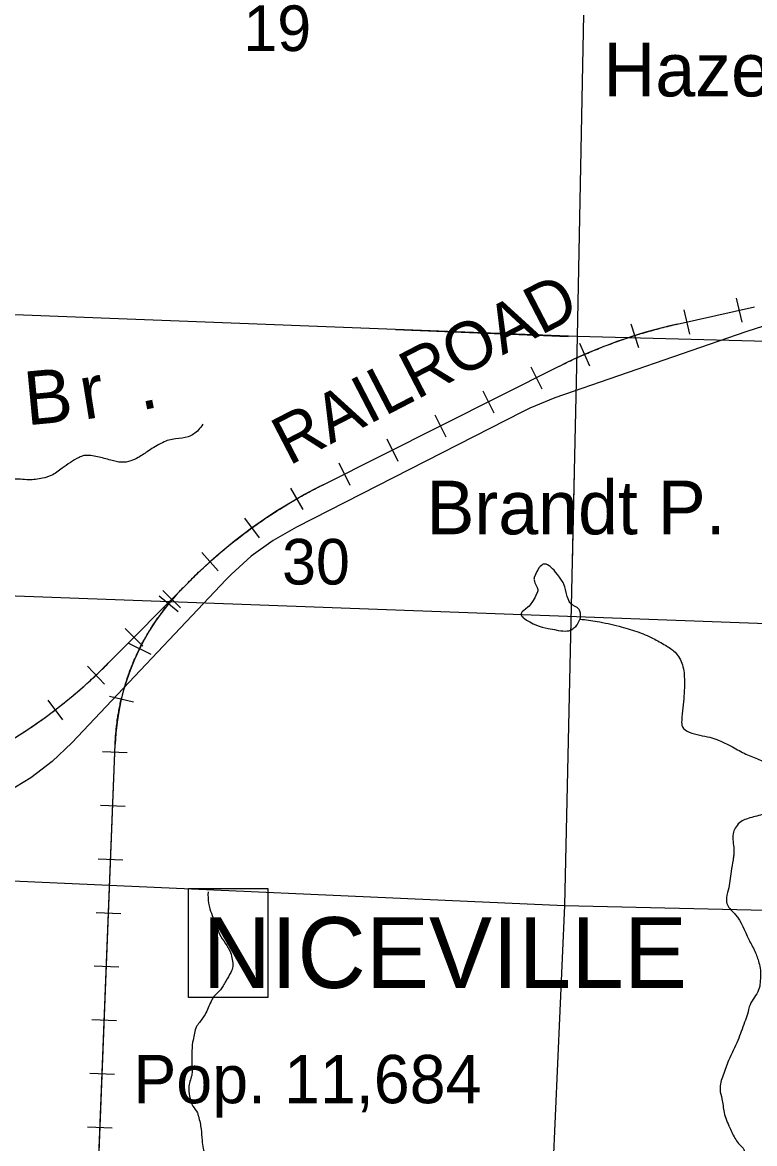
# Model space of a CAD drawing. Extents: x 1219626 to 1426462, y 456797 to 752399.
# Drawn here: x 1341318 to 1348140, y 566519 to 576968 of the extents above; entities that cross this region are included whole.
import ezdxf

# ---------------------------------------------------------------- set-up
doc = ezdxf.new("R2010")
doc.units = 0
for name, color, linetype in [('Cities Incorporated Area', 7, 'Continuous'), ('Lakes and Ponds', 7, 'Continuous'), ('Masks', 7, 'Continuous'), ('Masks for Text', 7, 'Continuous'), ('Narrow River Creek and Branch and Slough', 7, 'Continuous'), ('Narrow River Creek and Branch and Slough Text', 7, 'Continuous'), ('Other Incorporated Names', 7, 'Continuous'), ('Populations', 7, 'Continuous'), ('Railroads', 7, 'Continuous'), ('Railroads Text', 7, 'Continuous'), ('Section Lines', 7, 'Continuous'), ('Section Numbers', 7, 'Continuous')]:
    doc.layers.add(name, color=color, linetype=linetype)

msp = doc.modelspace()

# ---------------------------------------------------------------- linework, layer by layer
at = {"layer": 'Cities Incorporated Area'}
msp.add_line((1339773, 571677), (1348335, 571362), dxfattribs=at)
at = {"layer": 'Lakes and Ponds'}
msp.add_lwpolyline([(1346488, 571354), (1346503, 571384), (1346510, 571396), (1346515, 571408), (1346517, 571419), (1346519, 571430), (1346518, 571448), (1346517, 571462), (1346511, 571481), (1346508, 571489), (1346504, 571497), (1346496, 571506), (1346487, 571514), (1346469, 571525), (1346440, 571540), (1346428, 571549), (1346423, 571555), (1346418, 571560), (1346412, 571572), (1346402, 571595), (1346395, 571616), (1346385, 571655), (1346378, 571684), (1346372, 571707), (1346366, 571723), (1346355, 571747), (1346348, 571759), (1346341, 571771), (1346322, 571797), (1346303, 571822), (1346286, 571844), (1346271, 571862), (1346257, 571876), (1346245, 571888), (1346234, 571897), (1346225, 571904), (1346209, 571914), (1346197, 571918), (1346189, 571920), (1346176, 571919), (1346170, 571918), (1346165, 571915), (1346153, 571907), (1346142, 571897), (1346134, 571887), (1346120, 571867), (1346111, 571850), (1346098, 571823), (1346087, 571796), (1346085, 571788), (1346084, 571780), (1346085, 571772), (1346088, 571758), (1346093, 571745), (1346114, 571702), (1346117, 571691), (1346119, 571683), (1346120, 571671), (1346117, 571660), (1346103, 571628), (1346091, 571606), (1346071, 571572), (1346050, 571541), (1346039, 571528), (1346028, 571518), (1346005, 571500), (1345989, 571487), (1345978, 571478), (1345972, 571470), (1345968, 571465), (1345965, 571457), (1345964, 571449), (1345966, 571443), (1345969, 571438), (1345976, 571427), (1345985, 571418), (1345995, 571411), (1346014, 571398), (1346046, 571380), (1346077, 571364), (1346102, 571353), (1346123, 571345), (1346161, 571333), (1346218, 571320), (1346276, 571309), (1346309, 571302), (1346334, 571298), (1346352, 571296), (1346381, 571295), (1346395, 571296), (1346408, 571299), (1346420, 571302), (1346430, 571306), (1346446, 571315), (1346457, 571324), (1346473, 571338), (1346488, 571354)], dxfattribs=at)
at = {"layer": 'Masks'}
for p, q in [((1344795, 574105), (1346403, 574042)), ((1346458, 572776), (1346439, 571927))]:
    msp.add_line(p, q, dxfattribs=at)
at = {"layer": 'Masks for Text'}
msp.add_lwpolyline([(1342864, 568896), (1343604, 568896), (1343604, 567879), (1342864, 567879)], close=True, dxfattribs=at)
at = {"layer": 'Narrow River Creek and Branch and Slough'}
for points in [[(1343000, 573222), (1342958, 573170), (1342863, 573106), (1342745, 573086), (1342683, 573075), (1342624, 573051), (1342493, 572975), (1342396, 572913), (1342327, 572881), (1342241, 572868), (1342140, 572888), (1342016, 572919), (1341954, 572930), (1341891, 572930), (1341846, 572913), (1341687, 572812), (1341587, 572746), (1341504, 572719), (1341376, 572705), (1341227, 572708), (1341134, 572688), (1340926, 572688), (1340871, 572684), (1340795, 572733), (1340743, 572788), (1340646, 572895), (1340581, 572951), (1340439, 573041), (1340383, 573082), (1340325, 573131), (1340231, 573165), (1340089, 573172), (1339885, 573176), (1339816, 573151), (1339746, 573106), (1339677, 573048), (1339577, 572989), (1339515, 572926), (1339497, 572830), (1339518, 572774), (1339567, 572705), (1339636, 572663), (1339715, 572636), (1339736, 572594), (1339726, 572515), (1339670, 572421), (1339605, 572356), (1339504, 572297), (1339411, 572279), (1339297, 572300), (1339203, 572279), (1339127, 572255), (1339055, 572234), (1338999, 572196), (1338944, 572141), (1338889, 572131), (1338844, 572165), (1338778, 572224), (1338702, 572345), (1338643, 572418), (1338581, 572439), (1338470, 572525), (1338380, 572587), (1338308, 572629), (1338207, 572663), (1338014, 572698), (1337910, 572722), (1337685, 572798), (1337578, 572864), (1337481, 572944), (1337425, 572982), (1337297, 573003), (1337155, 572999), (1337010, 572975), (1336882, 572895), (1336813, 572837), (1336730, 572757), (1336619, 572670), (1336491, 572591), (1336426, 572560), (1336301, 572567), (1336166, 572608), (1335962, 572695), (1335834, 572743), (1335803, 572781), (1335717, 572816), (1335672, 572833), (1335617, 572819), (1335557, 572791)], [(1346514, 571407), (1346673, 571385), (1346877, 571340), (1347043, 571291), (1347195, 571226), (1347309, 571163), (1347399, 571098), (1347468, 570980), (1347486, 570831), (1347482, 570693), (1347461, 570464), (1347468, 570402), (1347531, 570354), (1347724, 570305), (1347935, 570215), (1348060, 570149), (1348181, 570098), (1348289, 570045), (1348351, 569983), (1348399, 569862), (1348406, 569779), (1348386, 569706), (1348347, 569657), (1348309, 569630), (1348254, 569602), (1348195, 569581), (1348064, 569543), (1348012, 569519), (1347967, 569471), (1347943, 569422), (1347946, 569280), (1347946, 569208), (1347939, 569163), (1347922, 569055), (1347894, 568882), (1347877, 568785), (1347894, 568730), (1347960, 568654), (1348085, 568422), (1348143, 568311), (1348181, 568204), (1348195, 568135), (1348195, 568093), (1348178, 567951), (1348098, 567813), (1348074, 567726), (1348047, 567650), (1347984, 567480), (1347898, 567294), (1347846, 567155), (1347818, 567024), (1347836, 566937), (1347856, 566809), (1347908, 566667), (1347964, 566557), (1348002, 566508), (1348040, 566463), (1348060, 566380), (1348077, 566347)], [(1343047, 568864), (1343052, 568760), (1343065, 568707), (1343095, 568624), (1343132, 568534), (1343155, 568472), (1343208, 568387), (1343257, 568299), (1343273, 568234), (1343278, 568170), (1343259, 568114), (1343213, 568034), (1343188, 567990), (1343162, 567951), (1343098, 567886), (1343075, 567842), (1343049, 567784), (1343019, 567722), (1342959, 567637), (1342932, 567593), (1342918, 567533), (1342904, 567464), (1342897, 567355), (1342897, 567226), (1342897, 567168), (1342869, 567055), (1342869, 567005), (1342886, 566919), (1342906, 566868), (1342948, 566806), (1342957, 566774), (1342973, 566712), (1342982, 566654), (1342992, 566550), (1343001, 566472), (1343015, 566428), (1343038, 566393), (1343061, 566379), (1343082, 566342), (1343077, 566310), (1343077, 566238), (1343089, 566201), (1343107, 566166), (1343160, 566131), (1343188, 566113), (1343225, 566044), (1343250, 565965), (1343273, 565887), (1343282, 565815), (1343298, 565769), (1343342, 565682), (1343391, 565580), (1343437, 565504), (1343480, 565415), (1343531, 565351), (1343584, 565265), (1343621, 565178), (1343646, 565058), (1343658, 565005), (1343672, 564975), (1343725, 564915), (1343759, 564882), (1343773, 564852), (1343799, 564780), (1343812, 564720), (1343810, 564677), (1343794, 564607), (1343778, 564570), (1343669, 564527), (1343582, 564487), (1343506, 564462), (1343434, 564418), (1343409, 564384), (1343374, 564328), (1343361, 564268), (1343344, 564208), (1343351, 564121), (1343361, 564017), (1343363, 563994), (1343340, 563938), (1343294, 563862), (1343238, 563779), (1343227, 563749), (1343218, 563666), (1343225, 563528), (1343225, 563470), (1343257, 563380), (1343280, 563276), (1343287, 563184), (1343278, 563092), (1343257, 562995)]]:
    msp.add_spline(points, degree=3, dxfattribs=at)
at = {"layer": 'Railroads'}
for p, q in [((1347969, 574397), (1348020, 574173)), ((1347420, 574156), (1348140, 574318)), ((1347481, 574288), (1347532, 574063)), ((1346988, 574159), (1347058, 573939)), ((1348057, 574085), (1346280, 573468)), ((1346509, 573979), (1346601, 573768)), ((1344119, 572659), (1346318, 573763)), ((1346054, 573759), (1346157, 573553)), ((1345607, 573534), (1345710, 573329)), ((1345977, 573339), (1343871, 572265)), ((1345160, 573310), (1345263, 573105)), ((1344713, 573086), (1344816, 572880)), ((1344266, 572862), (1344369, 572656)), ((1343817, 572627), (1343932, 572428)), ((1343387, 572349), (1343523, 572163)), ((1342989, 572027), (1343143, 571856)), ((1343217, 571776), (1341777, 570254)), ((1342118, 570996), (1342861, 571746)), ((1342627, 571673), (1342790, 571511)), ((1342592, 571624), (1342770, 571478)), ((1342275, 571318), (1342439, 571156)), ((1342307, 571183), (1342513, 571081)), ((1341924, 570967), (1342082, 570800)), ((1341553, 570651), (1341692, 570469)), ((1342128, 570690), (1342352, 570636)), ((1341961, 564672), (1342182, 570241)), ((1342064, 570172), (1342294, 570163)), ((1342044, 569673), (1342274, 569664)), ((1342024, 569173), (1342254, 569164)), ((1342005, 568674), (1342234, 568664)), ((1341985, 568174), (1342215, 568165)), ((1341965, 567674), (1342195, 567665)), ((1341945, 567175), (1342175, 567166)), ((1341925, 566675), (1342155, 566666))]:
    msp.add_line(p, q, dxfattribs=at)
for points in [[(1346693, 573931), (1346711, 573938), (1346730, 573946), (1346748, 573953), (1346766, 573960), (1346785, 573967), (1346803, 573973), (1346821, 573980), (1346840, 573987), (1346858, 573994), (1346877, 574000), (1346895, 574007), (1346914, 574013), (1346932, 574019), (1346951, 574026), (1346969, 574032), (1346988, 574038), (1347007, 574044), (1347025, 574050), (1347044, 574056), (1347063, 574061), (1347081, 574067), (1347100, 574073), (1347119, 574078), (1347138, 574084), (1347157, 574089), (1347176, 574094), (1347194, 574100), (1347213, 574105), (1347232, 574110), (1347251, 574115), (1347270, 574120), (1347289, 574125), (1347308, 574130), (1347327, 574134), (1347346, 574139), (1347365, 574143), (1347384, 574148), (1347403, 574152), (1347420, 574156), (1348140, 574318)], [(1349704, 574058), (1349465, 574136), (1349219, 574188), (1348969, 574215), (1348718, 574215), (1348468, 574188), (1348223, 574136), (1348057, 574085)], [(1342889, 571774), (1342903, 571788), (1342917, 571802), (1342931, 571815), (1342945, 571829), (1342959, 571843), (1342973, 571856), (1342987, 571869), (1343002, 571883), (1343016, 571896), (1343031, 571909), (1343045, 571923), (1343060, 571936), (1343074, 571949), (1343089, 571962), (1343104, 571975), (1343118, 571988), (1343133, 572001), (1343148, 572013), (1343163, 572026), (1343178, 572039), (1343193, 572051), (1343208, 572064), (1343223, 572076), (1343238, 572089), (1343253, 572101), (1343269, 572113), (1343284, 572126), (1343299, 572138), (1343315, 572150), (1343330, 572162), (1343346, 572174), (1343361, 572186), (1343377, 572198), (1343392, 572210), (1343408, 572221), (1343424, 572233), (1343440, 572245), (1343456, 572256), (1343471, 572268), (1343487, 572279), (1343503, 572290), (1343519, 572302), (1343535, 572313), (1343552, 572324), (1343568, 572335), (1343584, 572346), (1343600, 572357), (1343617, 572368), (1343633, 572379), (1343649, 572389), (1343666, 572400), (1343682, 572411), (1343699, 572421), (1343715, 572432), (1343732, 572442), (1343749, 572452), (1343765, 572463), (1343782, 572473), (1343799, 572483), (1343816, 572493), (1343832, 572503), (1343849, 572513), (1343866, 572523), (1343883, 572533), (1343900, 572542), (1343917, 572552), (1343934, 572562), (1343952, 572571), (1343969, 572580), (1343986, 572590), (1344003, 572599), (1344020, 572608), (1344038, 572618), (1344055, 572627), (1344073, 572636), (1344090, 572645), (1344107, 572653), (1344119, 572659), (1346318, 573763), (1346335, 573771), (1346353, 573780), (1346371, 573789), (1346388, 573797), (1346406, 573806), (1346424, 573814), (1346441, 573822), (1346459, 573831), (1346477, 573839), (1346495, 573847), (1346513, 573855), (1346531, 573863), (1346549, 573871), (1346567, 573879), (1346585, 573886), (1346603, 573894), (1346621, 573902), (1346639, 573909), (1346657, 573917), (1346675, 573924), (1346693, 573931)], [(1346280, 573468), (1346047, 573373), (1345977, 573339)], [(1343871, 572265), (1343653, 572140), (1343450, 571992), (1343263, 571824), (1343217, 571776)], [(1341313, 570342), (1341329, 570353), (1341346, 570363), (1341362, 570374), (1341378, 570385), (1341395, 570396), (1341411, 570407), (1341427, 570418), (1341443, 570429), (1341459, 570440), (1341475, 570452), (1341491, 570463), (1341507, 570474), (1341523, 570486), (1341539, 570497), (1341555, 570509), (1341570, 570521), (1341586, 570532), (1341602, 570544), (1341617, 570556), (1341633, 570568), (1341648, 570580), (1341664, 570592), (1341679, 570604), (1341695, 570616), (1341710, 570628), (1341725, 570641), (1341740, 570653), (1341756, 570666), (1341771, 570678), (1341786, 570691), (1341801, 570703), (1341816, 570716), (1341831, 570729), (1341846, 570741), (1341860, 570754), (1341875, 570767), (1341890, 570780), (1341904, 570793), (1341919, 570806), (1341934, 570819), (1341948, 570832), (1341962, 570846), (1341977, 570859), (1341991, 570872), (1342005, 570886), (1342020, 570899), (1342034, 570913), (1342048, 570927), (1342062, 570940), (1342076, 570954), (1342090, 570968), (1342104, 570982), (1342118, 570995), (1342118, 570996), (1342861, 571746), (1342875, 571760), (1342889, 571774)], [(1342611, 571462), (1342619, 571472), (1342627, 571483), (1342635, 571493), (1342643, 571504), (1342651, 571514), (1342659, 571525), (1342668, 571535), (1342676, 571545), (1342685, 571556), (1342693, 571566), (1342702, 571576), (1342710, 571586), (1342719, 571596), (1342728, 571606), (1342736, 571616), (1342745, 571626), (1342754, 571636), (1342763, 571646), (1342772, 571655), (1342781, 571665), (1342790, 571675), (1342800, 571684), (1342809, 571694), (1342817, 571702)], [(1341961, 564672), (1342182, 570241), (1342182, 570254), (1342183, 570267), (1342184, 570281), (1342185, 570294), (1342185, 570307), (1342186, 570320), (1342187, 570334), (1342189, 570347), (1342190, 570360), (1342191, 570373), (1342192, 570386), (1342194, 570400), (1342195, 570413), (1342197, 570426), (1342199, 570439), (1342200, 570452), (1342202, 570465), (1342204, 570479), (1342206, 570492), (1342208, 570505), (1342210, 570518), (1342213, 570531), (1342215, 570544), (1342217, 570557), (1342220, 570570), (1342222, 570583), (1342225, 570596), (1342228, 570609), (1342230, 570622), (1342233, 570635), (1342236, 570648), (1342239, 570661), (1342242, 570674), (1342246, 570687), (1342249, 570699), (1342252, 570712), (1342256, 570725), (1342259, 570738), (1342263, 570751), (1342266, 570763), (1342270, 570776), (1342274, 570789), (1342278, 570802), (1342282, 570814), (1342286, 570827), (1342290, 570840), (1342294, 570852), (1342298, 570865), (1342302, 570877), (1342307, 570890), (1342311, 570902), (1342316, 570915), (1342320, 570927), (1342325, 570940), (1342330, 570952), (1342335, 570964), (1342340, 570977), (1342345, 570989), (1342350, 571001), (1342355, 571013), (1342360, 571026), (1342365, 571038), (1342371, 571050), (1342376, 571062), (1342382, 571074), (1342387, 571086), (1342393, 571098), (1342399, 571110), (1342405, 571122), (1342410, 571134), (1342416, 571146), (1342422, 571158), (1342429, 571169), (1342435, 571181), (1342441, 571193), (1342447, 571204), (1342454, 571216), (1342460, 571228), (1342467, 571239), (1342473, 571251), (1342480, 571262), (1342486, 571274), (1342493, 571285), (1342500, 571296), (1342507, 571308), (1342514, 571319), (1342521, 571330), (1342528, 571341), (1342535, 571353), (1342543, 571364), (1342550, 571375), (1342557, 571386), (1342565, 571397), (1342572, 571408), (1342580, 571419), (1342588, 571429), (1342595, 571440), (1342603, 571451), (1342611, 571462)], [(1341777, 570254), (1341595, 570081), (1341396, 569928), (1341182, 569796), (1340956, 569687), (1340719, 569603), (1340475, 569544), (1340226, 569511), (1340076, 569504)]]:
    msp.add_lwpolyline(points, dxfattribs=at)
for centre, radius, start, end in [((1348471, 569472), 4800, 102.6415, 116.6471), ((1346272, 568369), 4800, 116.6471, 135.2842), ((1344380, 570154), 2200, 135.2778, 177.7285), ((1338707, 574373), 4800, 273.1744, 315.2842)]:
    msp.add_arc(centre, radius, start, end, dxfattribs=at)
at = {"layer": 'Section Lines'}
for p, q in [((1346590, 579314), (1346486, 574039)), ((1346486, 574039), (1341079, 574249)), ((1346486, 574039), (1346368, 568739)), ((1351782, 573901), (1346486, 574039)), ((1340970, 568978), (1346368, 568739)), ((1346368, 568739), (1346144, 563596)), ((1346368, 568739), (1351631, 568611))]:
    msp.add_line(p, q, dxfattribs=at)

# ---------------------------------------------------------------- texts
at = {"layer": 'Narrow River Creek and Branch and Slough Text'}
for s, rotation, p in [('Hazelwood P.', 359.9998, (1346732, 576278)), ('B', 5.4338, (1341358, 573212)), ('r', 9.1163, (1341891, 573264)), ('.', 11.3707, (1342420, 573350)), ('Brandt P.', 359.9998, (1345083, 572197))]:
    msp.add_text(s, height=500, rotation=rotation, dxfattribs=at).set_placement(p)
at = {"layer": 'Other Incorporated Names'}
msp.add_text('NICEVILLE', height=660, dxfattribs=at).set_placement((1342997, 567969))
at = {"layer": 'Populations'}
msp.add_text('Pop. 11,684', height=450, dxfattribs=at).set_placement((1342350, 566895))
at = {"layer": 'Railroads Text'}
msp.add_text('RAILROAD', height=450, rotation=27.3902, dxfattribs=at).set_placement((1343801, 572833))
at = {"layer": 'Section Numbers'}
for s, p in [('19', (1343376, 576701)), ('30', (1343737, 571729))]:
    msp.add_text(s, height=425, rotation=359.9998, dxfattribs=at).set_placement(p)

doc.saveas('drawing.dxf')
